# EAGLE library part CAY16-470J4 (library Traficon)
Resistor net Bourns RS reference: 241-9579
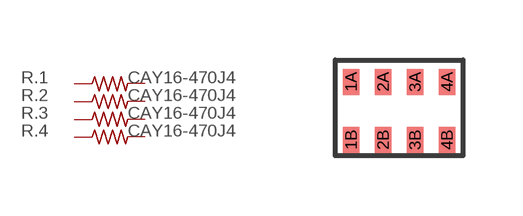
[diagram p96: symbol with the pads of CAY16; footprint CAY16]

Designator prefix R; gates .1=R_US .2=R_US .3=R_US .4=R_US

## CAY16-470J4  [CAY16]
1A  .1:1A  pas
1B  .1:1B  pas
2A  .2:1A  pas
2B  .2:1B  pas
3A  .3:1A  pas
3B  .3:1B  pas
4A  .4:1A  pas
4B  .4:1B  pas

## Footprint CAY16 (pad centres in mm)
smd 0.42 x 0.65: 1A 0,1.45; 1B 0,0; 2A 0.8,1.45; 2B 0.8,0; 3A 1.6,1.45; 3B 1.6,0; 4A 2.4,1.45; 4B 2.4,0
